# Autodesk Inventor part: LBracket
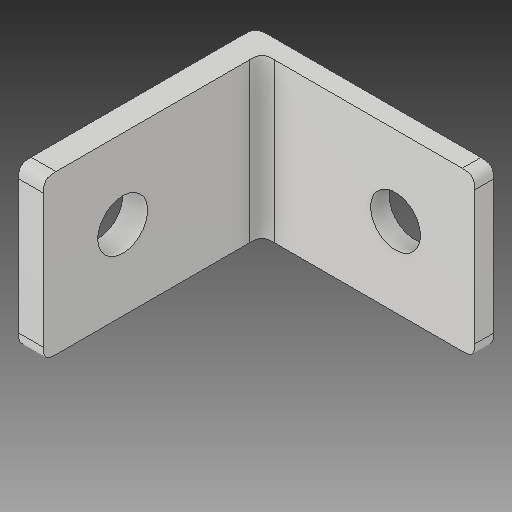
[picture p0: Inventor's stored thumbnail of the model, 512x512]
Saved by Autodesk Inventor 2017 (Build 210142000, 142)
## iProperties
Created: 2017-05
Part Number: LBracket
Material: Generic
Document SubType Name: Modeling
Designer: Savy
Density: 1 g/cm^3
Appearance: Default
Author: Savy
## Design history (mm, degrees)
feature "Base1"
body "Solid1"
